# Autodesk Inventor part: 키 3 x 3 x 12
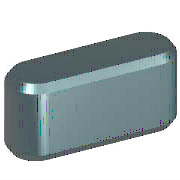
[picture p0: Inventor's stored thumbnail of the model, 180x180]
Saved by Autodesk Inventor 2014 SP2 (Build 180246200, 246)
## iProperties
Created: 2012-02
Part Number: 키 3 x 3 x 12
Material: 강철, 연강
Description: 키 및 해당 키홈
Document SubType Name: Modeling
Standard: KS B 1311
Designer: mduedu
Standards Organization: KS
Language: ko-KR
Size Designation: 3 x 3 x 12
Categories: <MemberInstance><Categories><Category DisplayName="샤프트 부품" InternalName="7f7aeb1f-a693-4053-b835-cee3144e0d98" Mnemonic="SHFT"><Category DisplayName="키" Interna
Density: 1 g/cm^3
Appearance: 노란색
IsCustomPart: 1
Author: mduedu
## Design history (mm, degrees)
workplane "Work Plane1"
workplane "Work Plane2"
sketch "스케치1"
  geometry: L1 (1.5, 1.5)-(10.5, 1.5); L2 (10.5, -1.5)-(1.5, -1.5); L3 (0, 9.4)-(0, -7.4) reference; L4 (-5, 0)-(30, 0) reference; L5 (12, 0)-(12, 7); A1 r 1.5 centre (1.5, 0) between (1.5, 1.5) and (1.5, -1.5); A2 r 1.5 centre (10.5, 0) between (10.5, -1.5) and (10.5, 1.5)
  constraints: 6 end point, 5 point on circle, 4 tangent, 3 point on line, 2 centre point, 1 horizontal, 1 parallel, 1 perpendicular
  dimensions: "d0" = 1.5 radius of A1 (= 0.5 x PB); "d13" = 1.5 radius of A2 (= 0.5 x PB); "d14" = 12 distance between parallel lines of L5 L3 (= NLG)
extrude "본체1" new body sketch "스케치1" taper "d3" = 0 deg; stored distance "d4" = 10
workplane "Work Plane3"
body "Solid1"
chamfer "모따기1" distance "d8" = 0.25 (= PHH); stored, may be unused: second distance "d9" = 0.25 (= PHH), angle "d15" = 45 deg
other parameters: "d1" = -1.8 (= -PNT), "d2" = 1.2 (= PH - PNT), "NLG" = 12 [user parameter; used in 3 equation terms], "PB" = 3 [user parameter; used in 2 equation terms], "PNT" = 1.8 [user parameter; used in 2 equation terms], "PH" = 3 [user parameter; used in 1 equation term], "PHH" = 0.25 [user parameter; used in 2 equation terms], "d10" = 0, "d16" = 0, "d17" = 0, "d18" = 0, "WDMIN" = 8 [user parameter], "PLB2" = 12 (= NLG) [user parameter], "PLB1" = 12 (= NLG) [user parameter], "RR" = 0.08 [user parameter], "PUEB" = 1.4 [user parameter]
